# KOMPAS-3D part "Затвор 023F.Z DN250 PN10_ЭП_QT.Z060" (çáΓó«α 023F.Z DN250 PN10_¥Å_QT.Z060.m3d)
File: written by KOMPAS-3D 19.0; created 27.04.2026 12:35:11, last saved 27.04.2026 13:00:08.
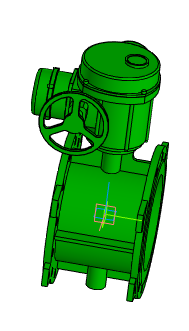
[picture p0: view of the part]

Document properties: Полное имя файла: Затвор 023F.Z DN250 PN10 + электропривод QT.Z060.a3d

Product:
- Part/product: Затвор 023F.Z DN250 PN10_ЭП_QT.Z060
    Масса: 129.608
  - Body: Тело 1
      Масса: 129.909

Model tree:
1. Операция без истории:1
